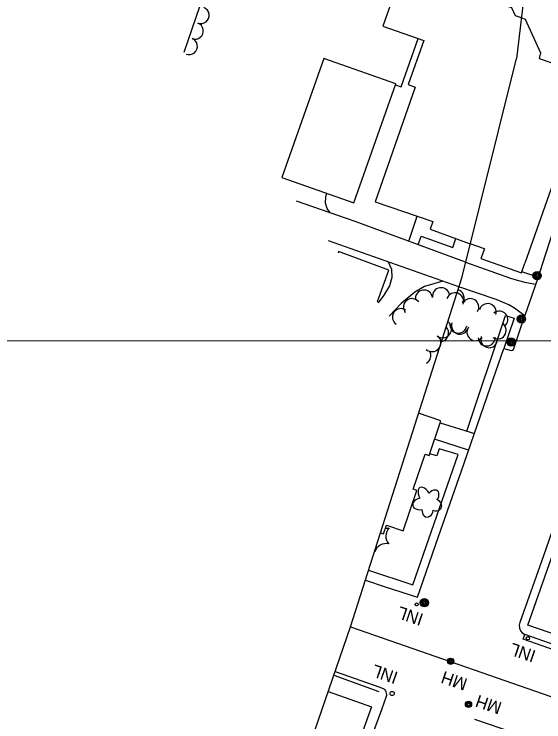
# Model space of a CAD drawing. Extents: x 189384 to 193282, y 256970 to 260388.
# Drawn here: x 190295.2 to 190551.4, y 258826.9 to 259169.2 of the extents above; entities that cross this region are included whole.
import ezdxf

# ---------------------------------------------------------------- set-up
doc = ezdxf.new("R2010")
doc.units = 0
for name, color, linetype in [('E_DRN_Grate', 7, 'Continuous'), ('E_DWY', 7, 'Continuous'), ('E_LAND_Vegetation', 7, 'Continuous'), ('E_MAP_GridLines', 7, 'Continuous'), ('E_MAP_Limits', 7, 'Continuous'), ('E_MISCPROP', 7, 'Continuous'), ('E_MISCPROP_HvyLine', 7, 'Continuous'), ('E_MISCPROP_Railing', 7, 'Continuous'), ('E_PATH_Sidewalk', 7, 'Continuous'), ('E_RDWY', 7, 'Continuous')]:
    doc.layers.add(name, color=color, linetype=linetype)

# ---------------------------------------------------------------- blocks, each defined once
blk = doc.blocks.new('INL_6')
at = {"layer": 'E_MISCPROP_Railing'}
blk.add_text('INL', height=6, rotation=359.9999, dxfattribs=at).set_placement((-5.79, -2.75))
blk = doc.blocks.new('POLE')
at = {"layer": 'E_MISCPROP'}
for radius in [2.02, 1.51, 1.01, 0.504]:
    blk.add_circle((0.03, -0.09), radius, dxfattribs=at)
blk = doc.blocks.new('TREE')
at = {"layer": 'E_LAND_Vegetation'}
for centre, major_axis, ratio in [((-1.07, 3.38), (0.91, -3.32), 0.782863), ((2.88, 1.66), (-3.52, -1.95), 0.691916), ((-3.74, -0.07), (3.29, -0.08), 0.832022), ((-1.48, -3.66), (1.2, 3.24), 0.716896), ((2.54, -2.64), (-3.34, 3.06), 0.560249)]:
    blk.add_ellipse(centre, major_axis=major_axis, ratio=ratio, start_param=1.570796, end_param=4.712389, dxfattribs=at)
blk = doc.blocks.new('INL_3')
at = {"layer": 'E_MISCPROP_Railing'}
blk.add_text('INL', height=6, rotation=0.0001, dxfattribs=at).set_placement((-5.79, -2.75))
blk = doc.blocks.new('MHO_5')
at = {"layer": 'E_DRN_Grate'}
for centre, radius in [((0.04, -0.06), 1.5), ((0.04, -0.06), 1.22), ((0.04, -0.07), 0.968), ((0.01, -0.08), 0.605)]:
    blk.add_circle(centre, radius, dxfattribs=at)

msp = doc.modelspace()

# ---------------------------------------------------------------- linework, layer by layer
at = {"layer": 'E_DWY'}
for points in [[(190444.48, 259237.49), (190442.51, 259230.99), (190427.8, 259235.7), (190408.66, 259242.02), (190377.27, 259150.66)], [(190479.62, 259134.92), (190482.51, 259134.03), (190490.66, 259157.41)], [(190448.08, 259073.09), (190446.63, 259075.16), (190445.79, 259077.82), (190446, 259080.99), (190446.53, 259082.54)], [(190513.62, 259049.22), (190460.17, 259068.86), (190431.86, 259078.77)], [(190510.33, 259037.35), (190447.32, 259059.51)], [(190476.19, 259049.36), (190477.78, 259045.76), (190477.98, 259041.8), (190476.81, 259037.81), (190474.05, 259033.26), (190471.33, 259029.61)], [(190513.62, 259049.22), (190535.35, 259041.47), (190538.57, 259040.5), (190542.88, 259039.47), (190547.63, 259038.64)], [(190513.62, 259049.22), (190535.35, 259041.47), (190538.57, 259040.5), (190542.88, 259039.47), (190547.63, 259038.64)], [(190502.65, 259040.05), (190498.68, 259038.97), (190493.69, 259037.38), (190488.98, 259034.73), (190482.4, 259029.24), (190476.74, 259023.22), (190476.61, 259023.03)], [(190542.29, 259023.2), (190539.2, 259025.54), (190537.18, 259026.94), (190534.45, 259028.6), (190528.42, 259031.13), (190510.33, 259037.35)], [(190542.29, 259023.2), (190539.2, 259025.54), (190537.18, 259026.94), (190534.45, 259028.6), (190528.42, 259031.13), (190510.33, 259037.35)], [(190501.27, 258971.51), (190517.86, 258966.42)], [(190501.27, 258971.51), (190517.86, 258966.42)], [(190515.01, 258958.25), (190498.6, 258963.61)], [(190515.01, 258958.25), (190498.6, 258963.61)]]:
    msp.add_lwpolyline(points, dxfattribs=at)
at = {"layer": 'E_LAND_Vegetation'}
for centre, radius, start, end in [((190385.57, 259168.57), 4.01, 249.1603, 69.1603), ((190382.72, 259161.09), 4.01, 249.1603, 69.1603), ((190379.87, 259153.6), 4.01, 249.1603, 69.1603), ((190493.45, 259031.6), 4.15, 7.9393, 187.924), ((190501.68, 259032.74), 4.15, 7.9393, 187.924), ((190508.78, 259031.91), 4.11, 324.8071, 74.7292), ((190487.71, 259027.45), 4.15, 37.8248, 217.8095), ((190508.5, 259030.27), 4.15, 340.3901, 160.3747), ((190515.86, 259027.48), 4.11, 328.7676, 148.7676), ((190515.86, 259027.48), 4.11, 328.7676, 148.7676), ((190524.25, 259025.06), 4.11, 344.2629, 164.2629), ((190524.25, 259025.06), 4.11, 344.2629, 164.2629), ((190482.36, 259022.6), 4.15, 55.0636, 235.0483), ((190529.91, 259021.43), 4.11, 309.8731, 129.8731), ((190529.91, 259021.43), 4.11, 309.8731, 129.8731), ((190502.51, 259016.98), 4.31, 230.7665, 50.7512), ((190501.28, 259014.98), 4.11, 278.8696, 45.8091), ((190510.09, 259019.03), 4.11, 171.4223, 351.4223), ((190510.86, 259018.53), 4.11, 161.4223, 341.4223), ((190518.34, 259015.36), 4.11, 142.6991, 322.6991), ((190518.34, 259015.36), 4.11, 142.6991, 322.6991), ((190529.12, 259016.19), 4.11, 234.7335, 54.7335), ((190529.12, 259016.19), 4.11, 234.7335, 54.7335), ((190497.35, 259010.26), 4.31, 227.7509, 47.7356), ((190523.82, 259012.8), 4.11, 181.6938, 1.6938), ((190525.01, 259011.97), 4.11, 161.6938, 341.6938), ((190492.48, 259004.11), 4.31, 301.7982, 28.964), ((190496.63, 259007.74), 4.11, 333.9129, 350.7658), ((190475.39, 258926.33), 5.72, 264.5227, 282.1063), ((190475.39, 258926.33), 5.72, 264.5227, 282.1063), ((190480.73, 258916.78), 5.72, 136.3414, 222.1063), ((190480.73, 258916.78), 5.72, 136.3414, 222.1063), ((190475.13, 258907.38), 5.72, 76.3414, 162.1063), ((190475.13, 258907.38), 5.72, 76.3414, 162.1063), ((190464.19, 258907.53), 5.72, 16.3414, 19.2475), ((190464.19, 258907.53), 5.72, 16.3414, 19.2475)]:
    msp.add_arc(centre, radius, start, end, dxfattribs=at)
at = {"layer": 'E_MAP_GridLines'}
msp.add_line((190146.69, 259011.09), (191646.69, 259012.15), dxfattribs=at)
msp.add_line((190146.69, 259011.09), (191646.69, 259012.15), dxfattribs=at)
msp.add_line((190146.69, 259011.09), (191646.69, 259012.15), dxfattribs=at)
at = {"layer": 'E_MAP_Limits'}
for points in [[(190622.49, 259989.85), (190597.72, 259644.89), (190538.23, 259147.8)], [(190457.96, 258872.88), (190511.86, 259042.18), (190538.23, 259147.8)], [(190400.94, 258707.45), (190457.96, 258872.88)], [(190457.96, 258872.88), (191213.57, 258610.1)], [(190457.96, 258872.88), (191213.57, 258610.1)]]:
    msp.add_lwpolyline(points, dxfattribs=at)
at = {"layer": 'E_MISCPROP_HvyLine'}
for points in [[(190540.58, 259167.47), (190537.77, 259168.31), (190536.02, 259172.19), (190483.2, 259190.73), (190473.59, 259163.32), (190493.38, 259156.47), (190485.76, 259135.19), (190489.28, 259133.88), (190469.92, 259078.44), (190497.75, 259068.82), (190496.45, 259065.16), (190515.85, 259058.15)], [(190540.58, 259167.47), (190542.45, 259166.67), (190549.86, 259150.4), (190549.24, 259147.78), (190574.2, 259139.12), (190542.17, 259048.78)], [(190540.58, 259167.47), (190542.45, 259166.67), (190549.86, 259150.4), (190549.24, 259147.78), (190574.2, 259139.12), (190542.17, 259048.78)], [(190522.67, 259055.72), (190515.85, 259058.15)], [(190522.67, 259055.72), (190515.85, 259058.15)], [(190522.67, 259055.72), (190520.96, 259051.03), (190540.58, 259044.08), (190542.17, 259048.78)], [(190522.67, 259055.72), (190520.96, 259051.03), (190540.58, 259044.08), (190542.17, 259048.78)], [(190470.81, 259030.27), (190470.96, 259030.21), (190476.53, 259045.31), (190476.53, 259045.31), (190476.53, 259045.31), (190452.11, 259054.33), (190451.91, 259053.79)], [(190472.43, 258918.32), (190473.89, 258917.82), (190475.32, 258922.04), (190475.32, 258922.04), (190475.32, 258922.04), (190483.43, 258919.3), (190483.43, 258919.3), (190490.02, 258938.8), (190490.02, 258938.8), (190490.02, 258938.8), (190488.3, 258939.38), (190488.3, 258939.38), (190494.02, 258956.31), (190494.02, 258956.31), (190495.92, 258955.67), (190495.92, 258955.67), (190495.92, 258955.67), (190501.61, 258972.52), (190490.84, 258976.16)], [(190472.43, 258918.32), (190473.89, 258917.82), (190475.32, 258922.04), (190475.32, 258922.04), (190475.32, 258922.04), (190483.43, 258919.3), (190483.43, 258919.3), (190490.02, 258938.8), (190490.02, 258938.8), (190490.02, 258938.8), (190488.3, 258939.38), (190488.3, 258939.38), (190494.02, 258956.31), (190494.02, 258956.31), (190495.92, 258955.67), (190495.92, 258955.67), (190495.92, 258955.67), (190501.61, 258972.52), (190490.84, 258976.16)]]:
    msp.add_lwpolyline(points, dxfattribs=at)
msp.add_lwpolyline([(190459.53, 259077.95), (190479.81, 259135.46), (190479.81, 259135.46), (190479.81, 259135.46), (190444.97, 259147.74), (190424.7, 259090.23), (190424.7, 259090.23), (190424.7, 259090.23)], close=True, dxfattribs=at)
at = {"layer": 'E_MISCPROP_Railing'}
for centre, radius in [((190489.9, 258883.7), 0.747), ((190489.9, 258883.7), 0.747), ((190543.76, 258867.36), 0.821)]:
    msp.add_circle(centre, radius, dxfattribs=at)
msp.add_ellipse((190478.08, 258840.64), major_axis=(-0.952, 0.314), ratio=0.99981, dxfattribs=at)
at = {"layer": 'E_PATH_Sidewalk'}
for points in [[(190486.09, 259059.34), (190490.18, 259071.43)], [(190490.67, 259057.65), (190492.18, 259061.73), (190507.45, 259056.35), (190508.84, 259060.68)], [(190548.74, 259041.9), (190540.74, 259044.55)], [(190548.74, 259041.9), (190540.74, 259044.55)], [(190514.15, 258967.56), (190532.88, 259023.42), (190537.03, 259022.07), (190532.15, 259007.4)], [(190514.15, 258967.56), (190532.88, 259023.42), (190537.03, 259022.07), (190532.15, 259007.4)], [(190599.47, 258885.7), (190589.65, 258857.91), (190543.66, 258873.61), (190566.39, 258938.34), (190580.53, 258978.25)], [(190466.69, 258900.28), (190488.12, 258893.21), (190509.96, 258956.18), (190500.86, 258958.95), (190499.73, 258955.55), (190496.21, 258956.54)], [(190466.69, 258900.28), (190488.12, 258893.21), (190509.96, 258956.18), (190500.86, 258958.95), (190499.73, 258955.55), (190496.21, 258956.54)], [(190449.88, 258849.42), (190471.69, 258841.57)], [(190447.18, 258841.59), (190468.1, 258834.24), (190461.64, 258816.22), (190441.14, 258757.22), (190436.59, 258744.35), (190421.31, 258700.47)]]:
    msp.add_lwpolyline(points, dxfattribs=at)
at = {"layer": 'E_RDWY'}
for points in [[(190465.16, 258895.48), (190474.73, 258892.19), (190490.28, 258887.17), (190500.28, 258916), (190512.83, 258951.98), (190525.71, 258988.91), (190532.15, 259007.4), (190535.65, 259006.58), (190536.31, 259006.62), (190536.81, 259006.91), (190541.19, 259020.1), (190543.41, 259026.33), (190548.66, 259041.63), (190552.25, 259052.8), (190559.59, 259075.54), (190568.32, 259101.09)], [(190465.16, 258895.48), (190474.73, 258892.19), (190490.28, 258887.17), (190500.28, 258916), (190512.83, 258951.98), (190525.71, 258988.91), (190532.15, 259007.4), (190535.65, 259006.58), (190536.31, 259006.62), (190536.81, 259006.91), (190541.19, 259020.1), (190543.41, 259026.33), (190548.66, 259041.63), (190552.25, 259052.8), (190559.59, 259075.54), (190568.32, 259101.09)], [(190593.84, 259028.33), (190583.13, 258998.28), (190573.75, 258971.99), (190564.67, 258945.68), (190551.28, 258907.28), (190539.89, 258875.04), (190539.54, 258873.62), (190539.63, 258872.22), (190540.16, 258870.86), (190540.92, 258869.9), (190542.24, 258869.22)], [(190864.16, 258923.98), (190854.25, 258890.76), (190842.5, 258853.18), (190831.29, 258819.32), (190824.84, 258799.89), (190822.64, 258793.68), (190819.25, 258788.22), (190815.78, 258784.76), (190811.14, 258781.53), (190806.08, 258779.56), (190801.35, 258778.8), (190797.68, 258778.88), (190793.94, 258779.61), (190787.75, 258781.34), (190761.37, 258790.37), (190730.96, 258800.7), (190722.34, 258803.77), (190678.03, 258819.18), (190650.09, 258828.9), (190606.65, 258843.88), (190569.45, 258856.99), (190541.41, 258866.86), (190542.24, 258869.22)], [(190663.16, 258827), (190650.91, 258831.26), (190607.47, 258846.24), (190570.28, 258859.35), (190542.24, 258869.22)], [(190450.5, 258851.22), (190472.19, 258843.7), (190474.02, 258842.86), (190474.53, 258842.35), (190474.82, 258841.87), (190474.94, 258841.39), (190475.31, 258840.22), (190475.32, 258839.68), (190475.2, 258839.12), (190472.95, 258832.78), (190466.45, 258815.28)], [(190517.92, 258828.27), (190550.43, 258817.07), (190577.1, 258808.05), (190598.18, 258800.75), (190616.38, 258794.51), (190642.44, 258785.51), (190649.41, 258783.07), (190686.16, 258770.53), (190696.24, 258766.91)]]:
    msp.add_lwpolyline(points, dxfattribs=at)

# ---------------------------------------------------------------- block references
at = {"layer": 'E_DRN_Grate'}
for p, rotation in [((190506.29, 258856.23), 71.03735335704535), ((190514.93, 258835.39), 71.03735320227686)]:
    msp.add_blockref('MHO_5', p, dxfattribs=dict(at, rotation=rotation))
at = {"layer": 'E_LAND_Vegetation', "rotation": 161.13016562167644}
msp.add_blockref('TREE', (190495.24, 258932.95), dxfattribs=at)
msp.add_blockref('TREE', (190495.24, 258932.95), dxfattribs=at)
at = {"layer": 'E_MISCPROP'}
for p, rotation in [((190548.2, 259042.61), 161.13016468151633), ((190548.2, 259042.61), 161.13016468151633), ((190540.61, 259021.63), 161.13016481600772), ((190540.61, 259021.63), 161.13016481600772), ((190535.66, 259010.45), 161.13016490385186), ((190535.66, 259010.45), 161.13016490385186), ((190493.65, 258884.43), 161.13016564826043), ((190493.65, 258884.43), 161.13016564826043)]:
    msp.add_blockref('POLE', p, dxfattribs=dict(at, rotation=rotation))
at = {"layer": 'E_MISCPROP_Railing'}
for name, p, rotation in [('INL_6', (190487.29, 258878.18), 161.13016576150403), ('INL_6', (190487.29, 258878.18), 161.13016576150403), ('INL_6', (190541.66, 258860.47), 161.1301647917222), ('INL_3', (190474.98, 258850.04), 161.0373539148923)]:
    msp.add_blockref(name, p, dxfattribs=dict(at, rotation=rotation))

# ---------------------------------------------------------------- texts
at = {"layer": 'E_DRN_Grate'}
for p in [(190514.95, 258847.58), (190531.56, 258836.06)]:
    msp.add_text('MH', height=6, rotation=161.0374, dxfattribs=at).set_placement(p)

doc.saveas('drawing.dxf')
